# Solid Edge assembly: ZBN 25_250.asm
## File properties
Title: Zylinder
Author: bmolnar
Template: iso metric assembly.asm
Last saved by: bmolnar
Revision: 26
Application: Solid Edge
Username: bmolnar
Dokumentum tartalom típus: 1
Document Number: ZBN 25/250
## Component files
Profilrohr.par
Kolbenstange.par
Kit_2.par
Kit_1.par
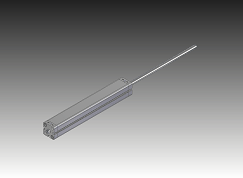
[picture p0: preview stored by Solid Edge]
